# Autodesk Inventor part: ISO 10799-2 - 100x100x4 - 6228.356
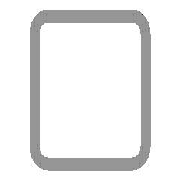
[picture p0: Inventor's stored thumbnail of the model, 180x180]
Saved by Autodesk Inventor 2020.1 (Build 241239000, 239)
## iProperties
Created: 2019-01
Part Number: ISO 10799-2 - 100x100x4 - 6228.356
Material: Stainless Steel
Description: Structural steels - Cold-formed, welded, structural hollow sections
Document SubType Name: Modeling
Standard: ISO
Designer: Synergysoft Dell02
Standard Revision: First edition 2011-09-15
Standards Organization: ISO
Language: en-US
Size Designation: 100x100x4
Categories: <MemberInstance><Categories><Category DisplayName="Structural Shapes" InternalName="089c4875-fa83-4c05-b084-43b9cc11f5ed" Mnemonic="GRDR"><CategoryParameter Dis
Stock Number: 100x100x4
Density: 8 g/cm^3
Appearance: Semi-Polished
_CCFamilyMember: 43
_CCFamilyDisplayName: ISO 10799-2 (Square) - Structural steels - Cold-formed, welded, structural hollow sections
_FrameMemberDoc: Frame Member File
_Version: 15.0.0
_GetPNFromCC: 1
G_L: 6228.356 mm
G_W: 100.000 mm
G_H: 100.000 mm
+C07F1630-128D-4BA2-99A7-A66D939FA75D+CUTDETAIL1: Miter 22.50 deg
+B4E8C4BE-60B8-4314-8C74-2DD17A406012+CUTDETAIL2: Miter 22.50 deg
IsCustomPart: 1
Author: Synergysoft Dell02
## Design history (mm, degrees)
node "Start Plane"
node "End Plane"
sketch "Sketch"
  geometry: L1 (-50, -42)-(-50, 42); L2 (-42, 50)-(42, 50); L3 (50, 42)-(50, -42); L4 (42, -50)-(-42, -50); L5 (-42, 46)-(42, 46); L6 (46, 42)-(46, -42); L7 (42, -46)-(-42, -46); L8 (-46, -42)-(-46, 42); L9 (0, 72.32)-(0, -72.32) reference; L10 (-72.32, 0)-(72.32, 0) reference; A1 r 8 centre (-42, -42) between (-50, -42) and (-42, -50); A2 r 8 centre (42, 42) between (50, 42) and (42, 50); A3 r 8 centre (-42, 42) between (-42, 50) and (-50, 42); A4 r 8 centre (42, -42) between (42, -50) and (50, -42); A5 r 4 centre (-42, 42) between (-42, 46) and (-46, 42); A6 r 4 centre (42, 42) between (46, 42) and (42, 46); A7 r 4 centre (42, -42) between (42, -46) and (46, -42); A8 r 4 centre (-42, -42) between (-46, -42) and (-42, -46)
  constraints: 16 end point, 16 point on circle, 8 centre point, 8 tangent, 4 parallel, 3 equal radius, 2 perpendicular, 7 other
  dimensions: "d7" = 8 radius of A1 (= G_IR); "d9" = 100 distance between parallel lines of L1 L3 (= G_W); "d11" = 100 distance between parallel lines of L2 L4 (= G_H); "d12" = 4 distance between parallel lines of L3 L6 (= G_T); "d15" = 50 distance between parallel lines of L9 L3 (= 0.5 x d9); "d16" = 50 distance between parallel lines of L2 L10 (= 0.5 x d11)
extrude "Body" new body sketch "Sketch" stored distance "d3" = 6228.35573 (= G_L); taper "d4" = 0 deg
node "Driven Length"
  sketch "Sketch3"
    geometry: L1 (0, 0)-(10, 0) reference
    constraints: 2 end point, 1 horizontal
  workplane "Work Plane3"
  sketch "Sketch4"
    geometry: L1 (-2, -114.178)-(12, -114.178) reference; L2 (-2, 6114.178)-(12, 6114.178) reference
    dimensions: "d18" = 6228.35573 distance between parallel lines of L1 L2 (derived)
workplane "Work Plane4"
split "Split1"
workplane "Work Plane5"
split "Split2"
body "Solid1"
other parameters: "G_W" = 100 [user parameter; used in 1 equation term], "G_H" = 100 [user parameter; used in 1 equation term], "G_T" = 4 [user parameter; used in 1 equation term], "G_IR" = 8 [user parameter; used in 1 equation term], "G_L" = 6228.35573 (= d18) [user parameter; used in 1 equation term], "G_OFFSET_START" = 114.17786 [user parameter; used in 1 equation term], "G_OFFSET_END" = 114.17786 [user parameter; used in 1 equation term], "d13" = -114.17786 (= -G_OFFSET_START), "d14" = 6114.17786 (= G_OFFSET_END + B_L), "d17" = 90 deg, "MAS" = 1.17 [user parameter]
